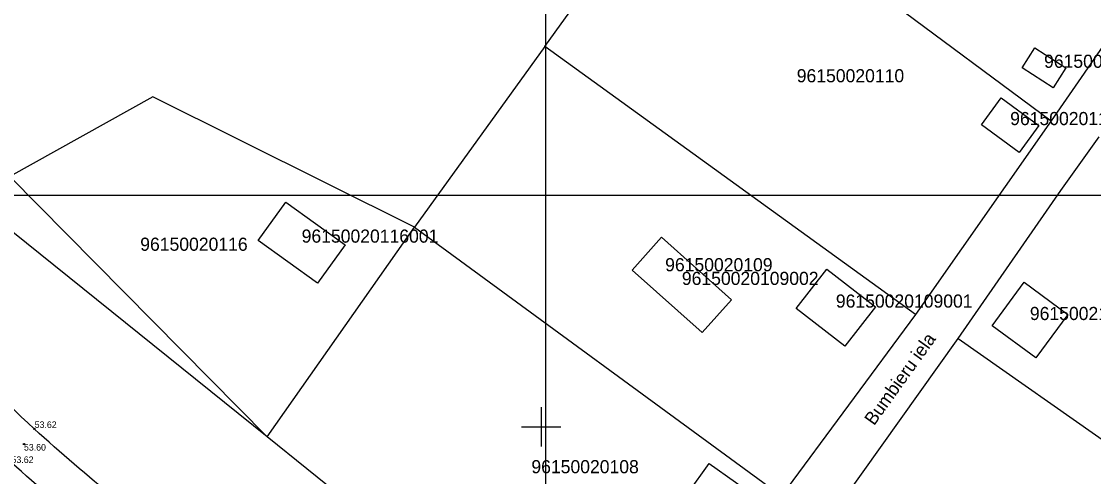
# Model space of a CAD drawing. Extents: x 578395 to 578590, y 418519 to 418816.
# Drawn here: x 578460.4 to 578542.1, y 418646.2 to 418680.8 of the extents above; entities that cross this region are included whole.
import ezdxf

# ---------------------------------------------------------------- set-up
doc = ezdxf.new("R2010")
doc.units = 0
for name, color, linetype in [('BUVE_EKAS_UZMR_####_#', 7, 'Continuous'), ('BUVE_EKAS_UZMR_TKST_#', 7, 'Continuous'), ('BUVE_EKAS_VEKT_####_#', 7, 'Continuous'), ('BUVE_EKAS_VEKT_TKST_#', 7, 'Continuous'), ('CELI_CMAL_####_####_#', 7, 'Continuous'), ('CELI_IELA_####_TKST_#', 7, 'Continuous'), ('GEOD_ELEM_####_####_#', 7, 'Continuous'), ('RAMI_PLAN_####_TKST_#', 7, 'Continuous'), ('RELJ_AATZ_####_TKST_#', 7, 'Continuous'), ('RELJ_ELEM_####_####_#', 7, 'Continuous'), ('ROBZ_PROJ_####_####_#', 7, 'Continuous'), ('ROBZ_PROJ_####_TKST_#', 7, 'Continuous'), ('ROBZ_UZMR_####_####_#', 7, 'Continuous'), ('ROBZ_UZMR_####_TKST_#', 7, 'Continuous')]:
    doc.layers.add(name, color=color, linetype=linetype)

msp = doc.modelspace()

# ---------------------------------------------------------------- linework, layer by layer
at = {"layer": 'BUVE_EKAS_UZMR_####_#'}
for p, q in [((578533.535, 418672.985), (578535.048, 418675.025)), ((578535.048, 418675.025), (578537.919, 418672.918)), ((578536.406, 418670.878), (578533.535, 418672.985)), ((578537.919, 418672.918), (578536.406, 418670.878)), ((578511.2, 418644.98), (578512.807, 418647.212)), ((578512.807, 418647.212), (578517.09, 418644.18))]:
    msp.add_line(p, q, dxfattribs=at)
at = {"layer": 'BUVE_EKAS_VEKT_####_#'}
for p, q in [((578536.637, 418677.323), (578537.611, 418678.829)), ((578537.611, 418678.829), (578539.977, 418677.299)), ((578539.003, 418675.793), (578536.637, 418677.323)), ((578539.977, 418677.299), (578539.003, 418675.793)), ((578478.461, 418664.17), (578480.566, 418667.093)), ((578480.566, 418667.093), (578485.07, 418663.85)), ((578482.964, 418660.926), (578478.461, 418664.17)), ((578485.07, 418663.85), (578482.964, 418660.926)), ((578506.946, 418661.929), (578509.169, 418664.418)), ((578509.169, 418664.418), (578514.497, 418659.659)), ((578512.274, 418657.17), (578506.946, 418661.929)), ((578519.438, 418658.997), (578521.761, 418662.002)), ((578521.761, 418662.002), (578525.463, 418659.14)), ((578534.346, 418657.695), (578536.785, 418661.004)), ((578536.785, 418661.004), (578540.109, 418658.553)), ((578514.497, 418659.659), (578512.274, 418657.17)), ((578523.14, 418656.135), (578519.438, 418658.997)), ((578525.463, 418659.14), (578523.14, 418656.135)), ((578540.109, 418658.553), (578537.671, 418655.245)), ((578537.671, 418655.245), (578534.346, 418657.695))]:
    msp.add_line(p, q, dxfattribs=at)
at = {"layer": 'CELI_CMAL_####_####_#'}
for points in [[(578540.02, 418586.371), (578525.988, 418597.847), (578512.594, 418608.642), (578501.669, 418618.235), (578486.368, 418629.744), (578473.85, 418639.529), (578461.404, 418649.849), (578445.482, 418664.308), (578434.891, 418671.618), (578433.593, 418673.245), (578433.709, 418674.571), (578434.344, 418682.513), (578433.832, 418698.668), (578431.508, 418715.146), (578429.961, 418730.384), (578428.634, 418741.31), (578426.857, 418755.172), (578424.464, 418771.373), (578422.35, 418787.381), (578420.601, 418802.682)], [(578422.643, 418673.344), (578426.408, 418667.598), (578432.023, 418657.972), (578440.378, 418642.229), (578453.358, 418623.699), (578463.599, 418609.382), (578465.428, 418605.837), (578466.347, 418604.486)], [(578433.603, 418667.727), (578433.533, 418667.219), (578433.834, 418664.827), (578435.716, 418660.389), (578444.472, 418644.493), (578457.112, 418626.41), (578467.85, 418611.554), (578470.384, 418608.861), (578471.211, 418607.779)], [(578538.092, 418583.58), (578523.866, 418595.463), (578510.65, 418606.122), (578499.131, 418615.129), (578484.947, 418627.43), (578472.156, 418636.888), (578459.663, 418647.262), (578443.345, 418661.302), (578436.955, 418666.057), (578434.564, 418667.369), (578433.603, 418667.727)]]:
    msp.add_spline(points, degree=3, dxfattribs=at)
at = {"layer": 'GEOD_ELEM_####_####_#'}
for p, q in [((578500, 418651.5), (578500, 418650)), ((578498.5, 418650), (578500, 418650)), ((578500, 418650), (578500, 418648.5)), ((578500, 418650), (578501.5, 418650))]:
    msp.add_line(p, q, dxfattribs=at)
at = {"layer": 'RAMI_PLAN_####_TKST_#'}
for p, q in [((578500.351, 418667.611), (578500.351, 418816.111)), ((578590.351, 418667.611), (578395.351, 418667.611)), ((578500.351, 418519.111), (578500.351, 418667.611))]:
    msp.add_line(p, q, dxfattribs=at)
at = {"layer": 'RELJ_ELEM_####_####_#'}
for centre in [(578461.404, 418649.849), (578460.617, 418648.695)]:
    msp.add_circle(centre, 0.05, dxfattribs=at)
at = {"layer": 'ROBZ_PROJ_####_####_#'}
for p, q in [((578539.594, 418667.97), (578542.492, 418672.062)), ((578531.777, 418656.722), (578539.594, 418667.97)), ((578528.523, 418658.549), (578518.31, 418644.74))]:
    msp.add_line(p, q, dxfattribs=at)
at = {"layer": 'ROBZ_UZMR_####_####_#'}
for p, q in [((578500.279, 418678.928), (578511.07, 418693.87)), ((578511.07, 418693.87), (578538.85, 418673.28)), ((578479.129, 418649.244), (578426.392, 418691.606)), ((578548.65, 418687.44), (578538.85, 418673.28)), ((578500.279, 418678.928), (578490.35, 418665.18)), ((578528.523, 418658.549), (578500.279, 418678.928)), ((578470.44, 418675.1), (578459.53, 418669.04)), ((578490.35, 418665.18), (578470.44, 418675.1)), ((578538.85, 418673.28), (578528.523, 418658.549)), ((578459.53, 418669.04), (578479.129, 418649.244)), ((578479.129, 418649.244), (578490.35, 418665.18)), ((578490.35, 418665.18), (578518.31, 418644.74)), ((578521.455, 418642.291), (578531.777, 418656.722)), ((578531.777, 418656.722), (578559.324, 418637.387)), ((578505.878, 418627.76), (578479.129, 418649.244))]:
    msp.add_line(p, q, dxfattribs=at)

# ---------------------------------------------------------------- texts
at = {"layer": 'BUVE_EKAS_UZMR_TKST_#'}
msp.add_text('96150020110001', height=1, dxfattribs=at).set_placement((578535.727, 418672.952))
at = {"layer": 'BUVE_EKAS_VEKT_TKST_#'}
for s, p in [('96150020111002', (578538.307, 418677.311)), ('96150020116001', (578481.766, 418664.01)), ('96150020109002', (578510.722, 418660.794)), ('96150020109001', (578522.451, 418659.069)), ('96150021303001', (578537.228, 418658.124))]:
    msp.add_text(s, height=1, dxfattribs=at).set_placement(p)
at = {"layer": 'CELI_IELA_####_TKST_#'}
msp.add_text('Bumbieru iela', height=1, rotation=54.42516, dxfattribs=at).set_placement((578525.361, 418650.042))
at = {"layer": 'RELJ_AATZ_####_TKST_#'}
for s, p in [('53.62', (578461.433, 418649.915)), ('53.60', (578460.617, 418648.195)), ('53.62', (578459.673, 418647.251))]:
    msp.add_text(s, height=0.5, dxfattribs=at).set_placement(p)
at = {"layer": 'ROBZ_PROJ_####_TKST_#'}
for s, p in [('96150020116', (578469.472, 418663.393)), ('96150020109', (578509.449, 418661.834))]:
    msp.add_text(s, height=1, dxfattribs=at).set_placement(p)
at = {"layer": 'ROBZ_UZMR_####_TKST_#'}
for s, p in [('96150020110', (578519.472, 418676.209)), ('96150020108', (578499.263, 418646.47))]:
    msp.add_text(s, height=1, dxfattribs=at).set_placement(p)

doc.saveas('drawing.dxf')
